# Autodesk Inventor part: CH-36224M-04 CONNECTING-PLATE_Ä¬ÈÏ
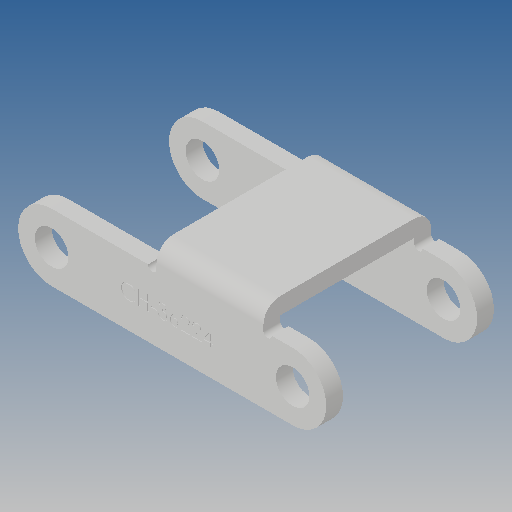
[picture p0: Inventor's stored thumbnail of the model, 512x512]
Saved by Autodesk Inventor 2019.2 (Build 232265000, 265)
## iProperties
Created: 2010-06
Part Number: CH-36224M-04 CONNECTING-PLATE_Ä¬ÈÏ
Material: Ogólny
Document SubType Name: Modeling
Designer: CADENGINEERING4
Density: 1 g/cm^3
Appearance: Domyślna
Author: CADENGINEERING4
Revision Number: ÈÎºÎ
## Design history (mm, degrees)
feature "NONE"
node "Bryła1"
